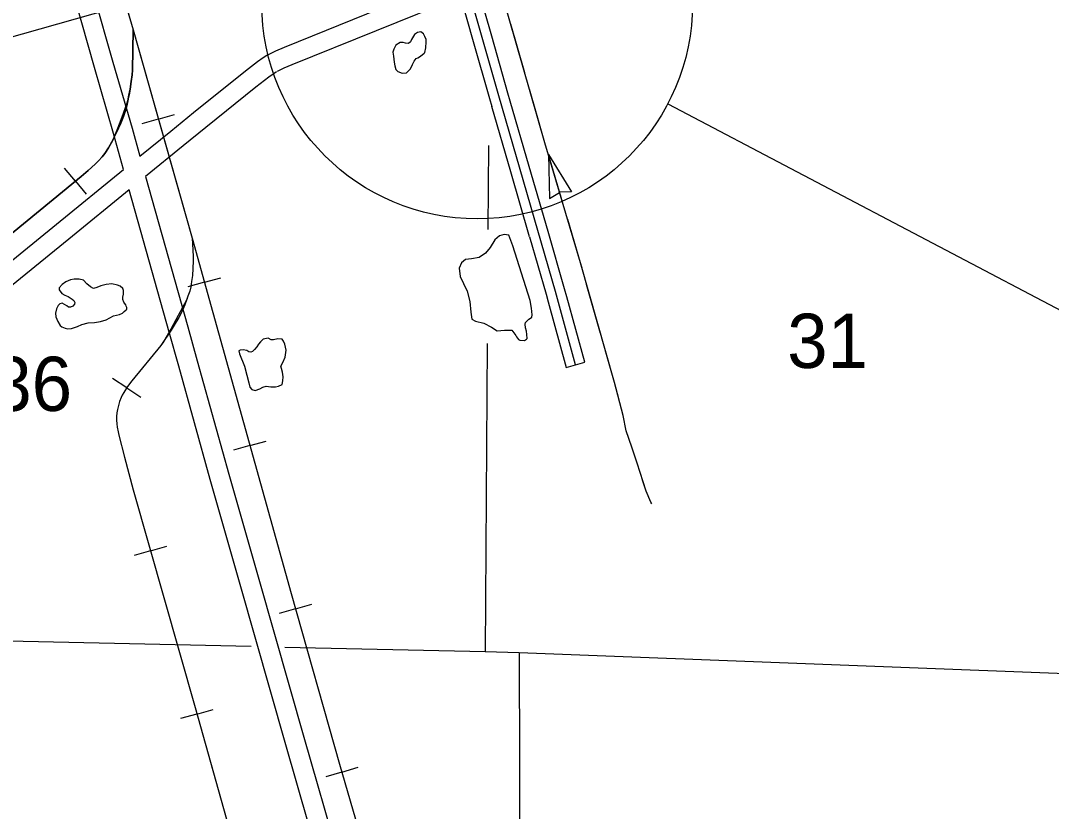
# Model space of a CAD drawing. Extents: x 1373094 to 1376427, y 1168361 to 1170494.
# Drawn here: x 1373442.4 to 1373576.1, y 1170158.6 to 1170261.2 of the extents above; entities that cross this region are included whole.
import ezdxf

# ---------------------------------------------------------------- set-up
doc = ezdxf.new("R2010")
doc.units = 0
doc.layers.add('R_Axis', color=7, linetype='Continuous')
doc.layers.add('R_Draft', color=7, linetype='Continuous')

msp = doc.modelspace()

# ---------------------------------------------------------------- linework, layer by layer
at = {"layer": 'R_Axis'}
for p, q in [((1373460.23, 1170248.38), (1373462.34, 1170248.98)), ((1373460.23, 1170248.38), (1373458.11, 1170247.78)), ((1373510.83, 1170243.79), (1373510.98, 1170238.07)), ((1373510.83, 1170243.79), (1373513.82, 1170238.92)), ((1373449.47, 1170240.32), (1373448.07, 1170242.01)), ((1373449.47, 1170240.32), (1373450.87, 1170238.62)), ((1373510.98, 1170238.07), (1373512.28, 1170238.87)), ((1373513.82, 1170238.92), (1373512.29, 1170238.88)), ((1373466.2, 1170227.2), (1373468.32, 1170227.8)), ((1373466.2, 1170227.2), (1373464.08, 1170226.61)), ((1373513.15, 1170216.16), (1373515.56, 1170216.83)), ((1373456.13, 1170213.5), (1373454.29, 1170214.71)), ((1373456.13, 1170213.5), (1373457.97, 1170212.29)), ((1373472.12, 1170206.01), (1373470, 1170205.42)), ((1373472.12, 1170206.01), (1373474.24, 1170206.61)), ((1373459.22, 1170192.36), (1373461.34, 1170192.96)), ((1373459.22, 1170192.36), (1373457.11, 1170191.76)), ((1373478.04, 1170184.83), (1373475.92, 1170184.23)), ((1373478.04, 1170184.83), (1373480.15, 1170185.43)), ((1373465.23, 1170171.19), (1373463.11, 1170170.6)), ((1373465.23, 1170171.19), (1373467.35, 1170171.79)), ((1373484.05, 1170163.66), (1373481.94, 1170163.05)), ((1373484.05, 1170163.66), (1373486.16, 1170164.28))]:
    msp.add_line(p, q, dxfattribs=at)
for points in [[(1373524.23, 1170198.47), (1373524.1, 1170198.69), (1373523.51, 1170200.1), (1373522.35, 1170203.74), (1373521.65, 1170205.8), (1373520.91, 1170207.92), (1373520.55, 1170209.9), (1373519.39, 1170214.19), (1373515, 1170229.71), (1373510.38, 1170245.3), (1373501.03, 1170277.83), (1373496.18, 1170294.91)], [(1373453.37, 1170272.22), (1373456.95, 1170259.94), (1373461.88, 1170242.54)], [(1373454.16, 1170269.52), (1373456.95, 1170259.94), (1373464.6, 1170232.93), (1373467.31, 1170223.27), (1373477.47, 1170186.82), (1373483.75, 1170164.69), (1373489.97, 1170143.28), (1373494.03, 1170129.36), (1373496.54, 1170120.87)], [(1373474.25, 1170256.62), (1373475.46, 1170257.24), (1373476.58, 1170257.71), (1373499.78, 1170267.13), (1373501.59, 1170267.78)], [(1373514.35, 1170216.5), (1373511.73, 1170226.02), (1373504.38, 1170251.41), (1373500.24, 1170265.97)], [(1373503.48, 1170259.15), (1373501.76, 1170265.19)], [(1373455.72, 1170241.82), (1373454.41, 1170246.5), (1373451.94, 1170255.09), (1373449.47, 1170263.78)], [(1373451.87, 1170264.47), (1373454.34, 1170255.78), (1373456.82, 1170247.18), (1373457.84, 1170243.55)], [(1373499.41, 1170264.28), (1373477.54, 1170255.4), (1373476.5, 1170254.97), (1373475.66, 1170254.54)], [(1373499.41, 1170264.28), (1373501.07, 1170258.46)], [(1373418.1, 1170214.6), (1373447.79, 1170238.93), (1373450.22, 1170240.93), (1373451.13, 1170241.7), (1373452.04, 1170242.53), (1373452.47, 1170242.97), (1373452.94, 1170243.48), (1373453.28, 1170243.9), (1373453.77, 1170244.65), (1373454.19, 1170245.42), (1373454.72, 1170246.48), (1373455.07, 1170247.2), (1373455.36, 1170247.84), (1373455.72, 1170248.73), (1373455.93, 1170249.37), (1373456.13, 1170250.11), (1373456.28, 1170250.73), (1373456.42, 1170251.46), (1373456.57, 1170252.27), (1373456.72, 1170253.25), (1373456.82, 1170254.12), (1373456.88, 1170254.73), (1373456.95, 1170259.94)], [(1373456.95, 1170259.94), (1373456.88, 1170254.73), (1373456.82, 1170254.12), (1373456.72, 1170253.25), (1373456.57, 1170252.27), (1373456.42, 1170251.46), (1373456.28, 1170250.73), (1373456.13, 1170250.11), (1373455.93, 1170249.37), (1373455.72, 1170248.73), (1373455.36, 1170247.84), (1373455.07, 1170247.2), (1373454.72, 1170246.48), (1373454.19, 1170245.42), (1373453.77, 1170244.65), (1373453.28, 1170243.9), (1373452.94, 1170243.48), (1373452.47, 1170242.97), (1373452.04, 1170242.53), (1373451.13, 1170241.7), (1373450.22, 1170240.93), (1373447.79, 1170238.93), (1373418.1, 1170214.6)], [(1373456.95, 1170259.94), (1373456.88, 1170254.73), (1373456.82, 1170254.12), (1373456.72, 1170253.25), (1373456.57, 1170252.27), (1373456.43, 1170251.52)], [(1373494.82, 1170257.03), (1373494.92, 1170257.61), (1373494.96, 1170258.4), (1373494.97, 1170258.7), (1373494.8, 1170259.1), (1373494.62, 1170259.45), (1373494.3, 1170259.71), (1373493.85, 1170259.62), (1373493.48, 1170259.35), (1373493.33, 1170259.13), (1373493.07, 1170258.69), (1373492.96, 1170258.42), (1373492.7, 1170258.18), (1373492.3, 1170258.22), (1373492, 1170258.3), (1373491.61, 1170258.3), (1373491.05, 1170257.97), (1373490.76, 1170257.43), (1373490.65, 1170257.06), (1373490.75, 1170256.55), (1373490.84, 1170255.78), (1373490.9, 1170255.28), (1373491.06, 1170254.82), (1373491.28, 1170254.55), (1373491.88, 1170254.33), (1373492.43, 1170254.39), (1373492.95, 1170254.88), (1373493.19, 1170255.48), (1373493.4, 1170255.9), (1373493.68, 1170256.23), (1373493.88, 1170256.33), (1373494.24, 1170256.55), (1373494.7, 1170256.91), (1373494.82, 1170257.03)], [(1373507.78, 1170254.36), (1373505.95, 1170260.7)], [(1373501.07, 1170258.46), (1373503.18, 1170251.06), (1373503.49, 1170249.99)], [(1373505.89, 1170250.69), (1373505.58, 1170251.75), (1373503.48, 1170259.15)], [(1373457.84, 1170243.55), (1373461.86, 1170246.83), (1373464.81, 1170249.23), (1373471.32, 1170254.47), (1373471.94, 1170254.94), (1373473.11, 1170255.85), (1373473.85, 1170256.36), (1373474.32, 1170256.66)], [(1373475.58, 1170254.5), (1373475.24, 1170254.28), (1373474.58, 1170253.83), (1373473.46, 1170252.96), (1373472.86, 1170252.5), (1373466.39, 1170247.29), (1373463.44, 1170244.9), (1373458.57, 1170240.92)], [(1373456.43, 1170251.52), (1373456.15, 1170250.44), (1373455.5, 1170248.61), (1373454.95, 1170247.15), (1373454.27, 1170245.56), (1373453.77, 1170244.65), (1373453.28, 1170243.9), (1373452.94, 1170243.48), (1373452.47, 1170242.97), (1373452.04, 1170242.53), (1373451.13, 1170241.7), (1373450.22, 1170240.93), (1373447.79, 1170238.93), (1373418.1, 1170214.6), (1373394.39, 1170195.12), (1373386.94, 1170189.03)], [(1373509.3, 1170249.08), (1373508.38, 1170252.25)], [(1373508.34, 1170242.24), (1373505.89, 1170250.69)], [(1373505.94, 1170241.54), (1373503.49, 1170249.99)], [(1373510.21, 1170245.9), (1373509.3, 1170249.08)], [(1373503.06, 1170244.96), (1373502.99, 1170234.07)], [(1373512.7, 1170237.46), (1373510.83, 1170243.79)], [(1373461.88, 1170242.54), (1373464.6, 1170232.93), (1373467.31, 1170223.27), (1373477.47, 1170186.82), (1373483.75, 1170164.69), (1373489.97, 1170143.28)], [(1373510.79, 1170233.78), (1373508.34, 1170242.24)], [(1373411.82, 1170205.99), (1373432.83, 1170223.19), (1373447.03, 1170234.73), (1373455.72, 1170241.82)], [(1373458.57, 1170240.92), (1373464.04, 1170221.42), (1373465.28, 1170217), (1373469.37, 1170202.29), (1373473.35, 1170188.39), (1373479.1, 1170168.17), (1373483.54, 1170152.71)], [(1373508.38, 1170233.09), (1373505.94, 1170241.54)], [(1373456.46, 1170239.2), (1373448.61, 1170232.79), (1373434.41, 1170221.25), (1373413.41, 1170204.05)], [(1373481.33, 1170151.35), (1373476.69, 1170167.49), (1373470.95, 1170187.7), (1373466.97, 1170201.61), (1373462.87, 1170216.33), (1373461.63, 1170220.75), (1373456.46, 1170239.2)], [(1373515.2, 1170229.03), (1373515, 1170229.71), (1373513.33, 1170235.36)], [(1373464.6, 1170232.93), (1373464.71, 1170231.42), (1373464.74, 1170230.5), (1373464.74, 1170229.93), (1373464.65, 1170228.07), (1373464.55, 1170227.32), (1373464.44, 1170226.61), (1373464.3, 1170226.03), (1373464.08, 1170225.39), (1373463.9, 1170224.9), (1373463.66, 1170224.29), (1373463.23, 1170223.29), (1373462.87, 1170222.63), (1373462.29, 1170221.63), (1373461.9, 1170221.01), (1373460.57, 1170219.02), (1373456.79, 1170214.42), (1373456.25, 1170213.69), (1373455.75, 1170212.92), (1373455.54, 1170212.57), (1373455.4, 1170212.26), (1373455.2, 1170211.72), (1373455.06, 1170211.23), (1373454.94, 1170210.7), (1373454.86, 1170210.26), (1373454.82, 1170209.78), (1373454.81, 1170209.33), (1373454.84, 1170208.86), (1373454.9, 1170208.39), (1373455.01, 1170207.81), (1373455.1, 1170207.39), (1373455.83, 1170204.53), (1373456.98, 1170200.26), (1373464.99, 1170172.04), (1373474.15, 1170139.51)], [(1373464.6, 1170232.93), (1373464.71, 1170231.42), (1373464.74, 1170230.5), (1373464.74, 1170229.93), (1373464.65, 1170228.07), (1373464.55, 1170227.32), (1373464.44, 1170226.61), (1373464.3, 1170226.03), (1373464.08, 1170225.39), (1373463.92, 1170224.95)], [(1373508.69, 1170222.69), (1373508.72, 1170222.96), (1373508.65, 1170223.84), (1373508.45, 1170224.84), (1373506.22, 1170231.95), (1373505.68, 1170233.3), (1373505.11, 1170233.39), (1373504.47, 1170233.24), (1373503.88, 1170232.7), (1373503.29, 1170231.71), (1373502.66, 1170230.99), (1373501.84, 1170230.41), (1373500.87, 1170230.23), (1373500.09, 1170230.14), (1373499.57, 1170229.74), (1373499.26, 1170229.02), (1373499.38, 1170227.97), (1373499.8, 1170227.06), (1373500.28, 1170226.03), (1373500.65, 1170224.7), (1373500.77, 1170223.33), (1373500.89, 1170222.42), (1373501.39, 1170222.16), (1373502.45, 1170221.91), (1373503.44, 1170221.37), (1373504.19, 1170220.92), (1373505.14, 1170221.01), (1373506.09, 1170220.98), (1373506.6, 1170220.32), (1373506.68, 1170220.14), (1373506.97, 1170219.77), (1373507.12, 1170219.69), (1373507.74, 1170219.67), (1373507.97, 1170219.84), (1373508.09, 1170219.92), (1373508.04, 1170220.42), (1373507.99, 1170220.84), (1373507.88, 1170221.31), (1373507.81, 1170221.76), (1373507.85, 1170221.99), (1373508.1, 1170222.26), (1373508.31, 1170222.42), (1373508.52, 1170222.55), (1373508.69, 1170222.69)], [(1373508.38, 1170233.09), (1373510.53, 1170225.68), (1373510.81, 1170224.65)], [(1373513.22, 1170225.31), (1373512.93, 1170226.36), (1373510.79, 1170233.78)], [(1373456.03, 1170224.26), (1373455.98, 1170224.34), (1373455.75, 1170224.64), (1373455.63, 1170224.95), (1373455.61, 1170225.29), (1373455.7, 1170225.67), (1373455.71, 1170226.14), (1373455.61, 1170226.39), (1373455.27, 1170226.7), (1373454.93, 1170226.84), (1373454.2, 1170227.02), (1373453.45, 1170226.92), (1373452.77, 1170226.76), (1373452.24, 1170226.54), (1373451.83, 1170226.4), (1373451.45, 1170226.61), (1373450.96, 1170227.02), (1373450.52, 1170227.48), (1373449.96, 1170227.62), (1373449.33, 1170227.61), (1373448.83, 1170227.5), (1373448.24, 1170227.26), (1373447.75, 1170226.93), (1373447.37, 1170226.49), (1373447.38, 1170226.21), (1373447.72, 1170225.73), (1373448.09, 1170225.54), (1373448.52, 1170225.34), (1373449.04, 1170225.03), (1373449.26, 1170224.84), (1373449.42, 1170224.57), (1373449.35, 1170224.37), (1373449.12, 1170224.12), (1373448.84, 1170223.98), (1373448.58, 1170223.99), (1373448.38, 1170224.15), (1373447.75, 1170224.51), (1373447.47, 1170224.39), (1373447.26, 1170224.17), (1373447.02, 1170223.75), (1373446.91, 1170223.2), (1373446.95, 1170222.73), (1373447.18, 1170222.11), (1373447.5, 1170221.6), (1373447.71, 1170221.44), (1373448.14, 1170221.23), (1373448.46, 1170221.18), (1373448.97, 1170221.21), (1373449.75, 1170221.45), (1373450.33, 1170221.71), (1373451.14, 1170221.93), (1373451.94, 1170221.97), (1373452.75, 1170222.12), (1373453.46, 1170222.33), (1373453.96, 1170222.6), (1373454.4, 1170222.85), (1373455.18, 1170223.04), (1373455.58, 1170223.21), (1373455.81, 1170223.4), (1373456.04, 1170223.62), (1373456.14, 1170223.71), (1373456.13, 1170223.94), (1373456.08, 1170224.11), (1373456.03, 1170224.26)], [(1373517.59, 1170220.56), (1373515.79, 1170226.91)], [(1373463.92, 1170224.95), (1373462.82, 1170222.89), (1373461.86, 1170221.12), (1373461.08, 1170219.76), (1373460.82, 1170219.33), (1373460.57, 1170219.02), (1373456.79, 1170214.42), (1373456.25, 1170213.69), (1373455.75, 1170212.92), (1373455.54, 1170212.57), (1373455.4, 1170212.26), (1373455.2, 1170211.72), (1373455.06, 1170211.23), (1373454.94, 1170210.7), (1373454.86, 1170210.26), (1373454.82, 1170209.78), (1373454.81, 1170209.33), (1373454.84, 1170208.86), (1373454.9, 1170208.39), (1373455.01, 1170207.81), (1373455.1, 1170207.39), (1373455.83, 1170204.53), (1373456.98, 1170200.26), (1373464.99, 1170172.04), (1373472.37, 1170145.82)], [(1373515.56, 1170216.83), (1373513.22, 1170225.31)], [(1373510.81, 1170224.65), (1373513.15, 1170216.16)], [(1373470.66, 1170218.33), (1373470.74, 1170217.9), (1373471.43, 1170216.34), (1373471.7, 1170215.17), (1373471.95, 1170214.14), (1373472.12, 1170213.61), (1373472.38, 1170213.3), (1373472.8, 1170213.15), (1373473.41, 1170213.4), (1373473.79, 1170213.6), (1373474.2, 1170213.73), (1373474.83, 1170213.65), (1373475.42, 1170213.65), (1373475.8, 1170213.74), (1373476.28, 1170213.96), (1373476.4, 1170214.41), (1373476.44, 1170214.93), (1373476.35, 1170215.55), (1373476.21, 1170216.01), (1373476.14, 1170216.3), (1373476.39, 1170216.8), (1373476.68, 1170217.47), (1373476.82, 1170218.38), (1373476.65, 1170219.19), (1373476.46, 1170219.56), (1373476.29, 1170219.81), (1373475.73, 1170219.85), (1373475.16, 1170219.72), (1373474.85, 1170219.73), (1373474.46, 1170219.94), (1373473.81, 1170219.82), (1373473.49, 1170219.46), (1373473.24, 1170219.19), (1373473, 1170218.85), (1373472.71, 1170218.48), (1373472.44, 1170218.24), (1373472.23, 1170218.12), (1373471.99, 1170218.2), (1373471.73, 1170218.36), (1373471.23, 1170218.42), (1373470.84, 1170218.4), (1373470.66, 1170218.33)], [(1373502.88, 1170219.25), (1373502.61, 1170179.31)], [(1373519.96, 1170212.08), (1373519.39, 1170214.19), (1373518.19, 1170218.44)], [(1373522.38, 1170203.64), (1373522.35, 1170203.74), (1373521.65, 1170205.8), (1373520.91, 1170207.92), (1373520.55, 1170209.9), (1373520.53, 1170209.96)], [(1373524.23, 1170198.47), (1373524.1, 1170198.69), (1373523.51, 1170200.1), (1373523.05, 1170201.54)], [(1373391.81, 1170181.39), (1373413.31, 1170181.21), (1373419.02, 1170181.15), (1373472.28, 1170179.98)], [(1373476.64, 1170179.88), (1373502.61, 1170179.31), (1373507.02, 1170179.18), (1373586.95, 1170176.1), (1373590.16, 1170175.98), (1373633.82, 1170174.77)], [(1373507.02, 1170179.18), (1373507.2, 1170120.87)]]:
    msp.add_lwpolyline(points, dxfattribs=at)
msp.add_lwpolyline([(1373436.01, 1170257.59), (1373474.1, 1170268.4), (1373470.5, 1170281.1), (1373432.41, 1170270.29)], close=True, dxfattribs=at)
at = {"layer": 'R_Draft'}
msp.add_line((1373526.32, 1170250.36), (1374006.35, 1169997.87), dxfattribs=at)
msp.add_circle((1373501.59, 1170263.37), 27.94, dxfattribs=at)

# ---------------------------------------------------------------- texts
at = {"layer": 'R_Axis'}
for s, p in [('31', (1373541.81, 1170216.09)), ('36', (1373438.57, 1170210.51))]:
    msp.add_text(s, height=7.04, dxfattribs=at).set_placement(p)

doc.saveas('drawing.dxf')
